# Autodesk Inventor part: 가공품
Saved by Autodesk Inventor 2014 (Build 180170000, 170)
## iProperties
Created: 2025-02
Part Number: 가공품
Material: 일반
Document SubType Name: Modeling
Designer: dg
Density: 1 g/cm^3
Appearance: 기본값
Author: dg
Author: jhkim
Creation Date: 2025-02-05
Sending System: Autodesk Inventor 2025
Preprocessor: ST-DEVELOPER v20
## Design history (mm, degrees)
node "가공품1"
node "솔리드1"
node "기준1"
